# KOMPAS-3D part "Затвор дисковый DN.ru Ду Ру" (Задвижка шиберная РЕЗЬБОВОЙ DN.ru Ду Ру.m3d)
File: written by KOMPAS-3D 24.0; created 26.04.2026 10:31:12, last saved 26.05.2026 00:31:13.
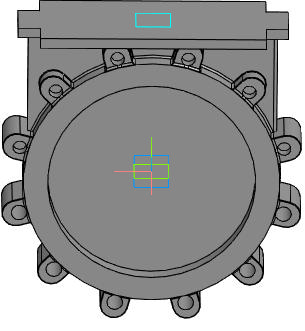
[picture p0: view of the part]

Document properties: Автор: R2D2; Полное имя файла: E:\Работа\Зайцев\GVKR1331M-1W-Fb-2P Задвижка шиберная с выдвижным штоком DN.ru Ду50-300 Ру16-10-6 с пневмоприводом\исходные материалы\DN300\Задвижка шиберная РЕЗЬБОВОЙ DN.ru Ду Ру.m3d

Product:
- Part/product: Затвор дисковый DN.ru Ду Ру
    Масса: 18.2
    Раздел спецификации: Прочие изделия
    Примечание: D050-23732

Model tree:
1. Смещенная плоскость:2
2. Диск
3. Корпус
4. Элемент выдавливания:3
     Расстояние 1 = 30
5. Элемент вращения:1
     Угол 1 = 360
6. Корпус штока
7. Элемент выдавливания:6  (with: Грань.Элемент вращения:1)
     Расстояние 1 = 237.5
8. Ушко  (with: Ребро.Элемент вращения:1)
9. Элемент выдавливания:5
10. Эскиз:1  (with: Ребро.Элемент выдавливания:5)
11. Элемент выдавливания:12
     Расстояние 1 = 38; Расстояние 2 = 38
12. Элемент выдавливания:13
13. Массив по концентрической сетке:2  (with: Элемент выдавливания:13, Эскиз:1, Элемент выдавливания:12, Элемент выдавливания:5, Грань.Элемент вращения:1)  (12 pattern instances)
     Шаг 2 = 360
14. Эскиз:2  (labels: Ребро.Элемент выдавливания:5.Экземпляр ( 1, 11 ))
15. Элемент выдавливания:14
16. Массив по концентрической сетке:3  (with: Элемент выдавливания:14, Эскиз:2, Грань.Элемент вращения:1)  (6 pattern instances)
     Шаг 2 = 30
17. площадка  (with: Грань.Элемент выдавливания:6, Ребро.Элемент выдавливания:5)
18. Элемент выдавливания:15
     Расстояние 2 = 15
19. Скругление:10  (with: Ребро.Элемент выдавливания:6)
     Радиус = 5
20. Эскиз:4  (labels: Задвижка шиберная с выдвижным штоком DN.ru Ду50 Ру16; Затвор дисковый DN.ru Ду200 Ру16)
21. Элемент выдавливания:16  (with: Грань.Элемент вращения:1)
     Расстояние 1 = 186; Смещение 1 = 1
22. Эскиз:5  (labels: Задвижка шиберная DN.ru Ду50 Ру10; Затвор дисковый DN.ru Ду200 Ру16)
23. Скругление:11  (with: Ребро.Элемент выдавливания:16)
     Радиус = 3
24. Элемент выдавливания:17  (with: Грань.Элемент вращения:1)
     Расстояние 1 = 185.99; Смещение 1 = 1
25. Массив по концентрической сетке:1  (with: Элемент выдавливания:5, Элемент выдавливания:13, Эскиз:1)  (5 pattern instances)
     Шаг 2 = 360
26. Скругление:17  (with: Грань.Элемент выдавливания:5)  (labels: Грань.Элемент выдавливания:5.Экземпляр ( 1, 4 ); Грань.Элемент выдавливания:5.Экземпляр ( 1, 3 ); Грань.Элемент выдавливания:5.Экземпляр ( 1, 2 ); Грань.Элемент выдавливания:5.Экземпляр ( 1, 5 ))
     Радиус = 1

Expressions: c-8-2*t; v1301/2; dd/2; d/2+40; 360/n*2+360/n
Referenced files in E:\Работа\Зайцев\GVKR1331E-1W-Fb-2P Задвижка шиберная DN.ru Ду50-300 Ру16-10-6\исходные материалы\DN50\: GVKR1331E-1W-Fb-2P Задвижка шиберная с выдвижным штоком DN.ru Ду50 Ру16.a3d, GVKR1331E-1W-Fb-2P Задвижка шиберная DN.ru Ду50 Ру16.a3d
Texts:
  Угловой размер с обрывом
  GOST 26.020 Pr3
  var3D
  ширина затвора по металлу
  площадка под крепеж
  DN+10
  dk+20
  dk-10
  Плоскость ZY.Начало координат
  Грань.Элемент выдавливания:5.Экземпляр ( 1, 6 )
  Грань.Элемент выдавливания:5.Экземпляр ( 1, 7 )
  Грань.Элемент выдавливания:5.Экземпляр ( 1, 8 )
  Грань.Элемент выдавливания:5.Экземпляр ( 1, 9 )
  Грань.Элемент выдавливания:5.Экземпляр ( 1, 10 )
  Грань.Элемент выдавливания:5.Экземпляр ( 1, 12 )
  Грань.Элемент выдавливания:5.Экземпляр ( 1, 11 )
